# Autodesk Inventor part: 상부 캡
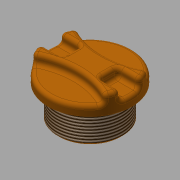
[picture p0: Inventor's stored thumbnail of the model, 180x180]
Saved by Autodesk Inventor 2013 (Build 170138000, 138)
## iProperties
Created: 2016-09
Part Number: 상부 캡
Material: ABS 플라스틱
Document SubType Name: Modeling
Designer: mduedu
Density: 1.06 g/cm^3
Mass: 23.0416 g
Surface Area: 69.3208 cm^2
Volume: 21.7373 cm^3
Author: mduedu
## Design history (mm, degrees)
sketch "스케치1"
  geometry: C1 r 22.5 at (0, 0); 1 further point
  constraints: 1 centre point, 1 coincident
  dimensions: "d0" = 45 diameter of C1
extrude "돌출1" new body sketch "스케치1" distance "d1" = 10; taper "d2" = 0 deg
sketch "스케치2" dims "d4" = 80
  geometry: C1 r 22.5 at (0, 0) reference; 3 further points
  constraints: 3 vertical alignment, 2 other
  dimensions: "d3" = 7 distance of point (0, 7) point (0, 0)
extrude "돌출2" cut sketch "스케치2" distance "d5" = 5; taper "d6" = 0 deg
sketch "스케치3"
  geometry: L1 (-22.5, 0)-(0, 0); L2 (-21.937, 5)-(-10, 5); L3 (-10, 5)-(-10, -5); L4 (-10, -5)-(-21.937, -5); A1 r 22.5 centre (0, 0) between (-19.118, 11.864) and (-19.118, -11.864) reference; A2 r 22.5 centre (0, 0) between (-21.937, 5) and (-21.937, -5); 1 further point
  constraints: 8 end point, 5 point on circle, 2 horizontal, 1 centre point, 1 coincident, 1 parallel, 1 perpendicular, 1 symmetric about line
  dimensions: "d7" = 10 distance from line of L3 point (0, 0); "d8" = 10 distance of L2.end L3.end
extrude "돌출3" cut sketch "스케치3" distance "d9" = 5; taper "d10" = 0 deg
fillet "모깎기1" dims "d11" = 2
fillet "모깎기2" dims "d12" = 2
fillet "모깎기3" dims "d13" = 2
sketch "스케치4"
  geometry: C1 r 17.5 at (0, 0); 1 further point
  constraints: 1 centre point, 1 coincident
  dimensions: "d14" = 35 diameter of C1
extrude "돌출4" join sketch "스케치4" distance "d15" = 17; taper "d16" = 0 deg
sketch "스케치5"
  geometry: C1 r 12.5 at (0, 0); 1 further point
  constraints: 1 centre point, 1 coincident
  dimensions: "d17" = 25 diameter of C1
extrude "돌출5" cut sketch "스케치5" distance "d18" = 10; taper "d19" = 0 deg
fillet "모깎기4" dims "d20" = 3
sketch "스케치6"
  geometry: L1 (0, 22.5)-(0, -22.5) reference; L2 (0, 17.5)-(-1, 17.5); L3 (-1, 17.5)-(-1, 16.5); L4 (-1, 16.5)-(0, 16.5); L5 (0, 16.5)-(0, 17.5); L6 (0, 17.5)-(-17, 17.5) reference; L7 (-22.401, 0)-(15.404, 0) reference; 1 further point
  constraints: 8 end point, 2 parallel, 1 collinear, 1 horizontal, 1 perpendicular, 1 point on line
  dimensions: "d26" = 1 distance of L2.start L2.end; "d28" = 1 distance of L2.end L3.end
revolve "회전1" sketch "스케치6" stored, may be unused: angle "d29" = 90 deg
feature "스레드1" dims "d21" = 10, "d22" = 0
chamfer "모따기1" distance "d23" = 1; stored, may be unused: second distance "d24" = 2, angle "d25" = 45 deg
chamfer "모따기2" distance "d30" = 1; stored, may be unused: second distance "d31" = 2, angle "d32" = 45 deg
node "솔리드1"
mirror "대칭1"
mirror "대칭2"
node "투영된 루프1"
